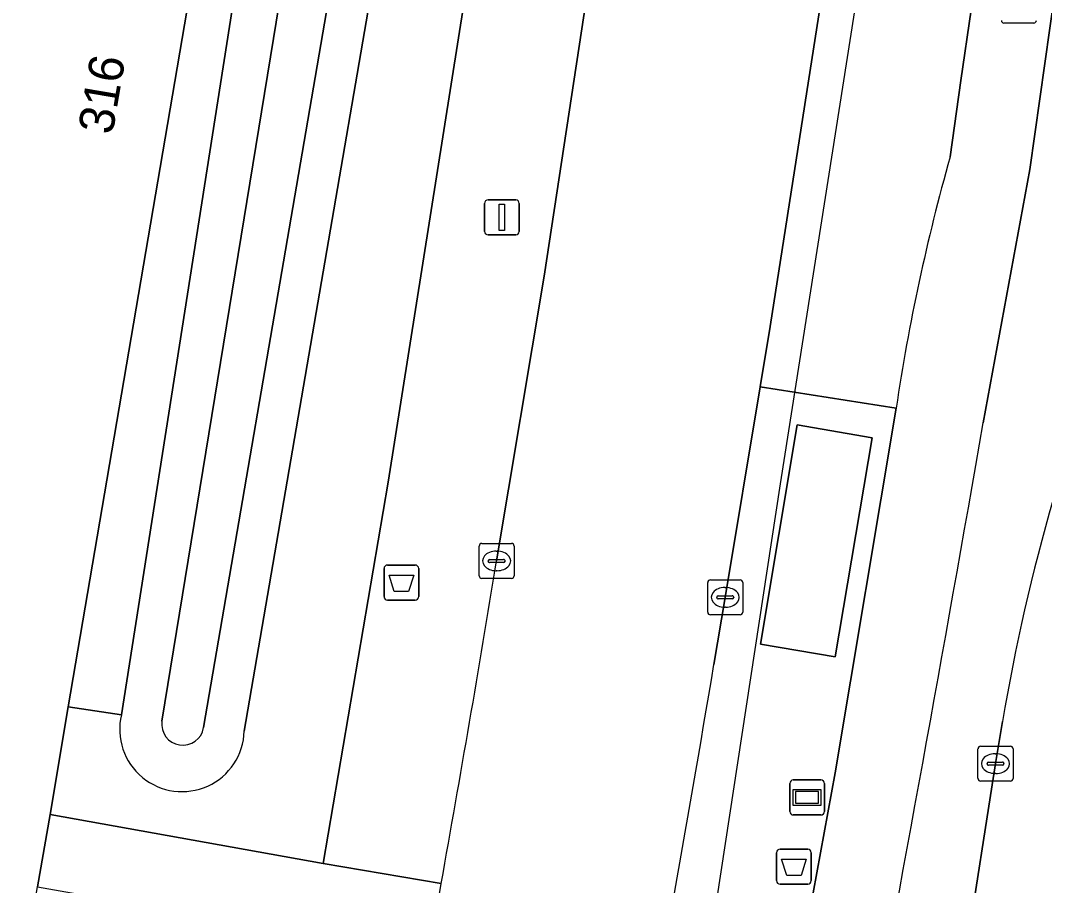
# Model space of a CAD drawing. Extents: x 161090 to 161692, y 379509 to 380907.
# Drawn here: x 161509.63 to 161538.89, y 379865.66 to 379890.39 of the extents above; entities that cross this region are included whole.
import ezdxf

# ---------------------------------------------------------------- set-up
doc = ezdxf.new("R2010")
doc.units = 0
for name, color, linetype in [('IMGEO_Afvalbak', 7, 'Continuous'), ('IMGEO_Berm_groen', 7, 'Continuous'), ('IMGEO_Fietspad_gesloten', 7, 'Continuous'), ('IMGEO_Groenvoorziening', 7, 'Continuous'), ('IMGEO_Hek', 7, 'Continuous'), ('IMGEO_Informatiebord', 7, 'Continuous'), ('IMGEO_Kolk', 7, 'Continuous'), ('IMGEO_Lichtmast', 7, 'Continuous'), ('IMGEO_Oever', 7, 'Continuous'), ('IMGEO_OVBaan_gesloten', 7, 'Continuous'), ('IMGEO_Pand', 7, 'Continuous'), ('IMGEO_Pand_nummerreeks', 7, 'Continuous'), ('IMGEO_Rijbaan_regionaal_gesloten', 7, 'Continuous'), ('IMGEO_Rioolput', 7, 'Continuous'), ('IMGEO_Voetpad_open', 7, 'Continuous'), ('IMGEO_Waterloop', 7, 'Continuous')]:
    doc.layers.add(name, color=color, linetype=linetype)

msp = doc.modelspace()

# ---------------------------------------------------------------- linework, layer by layer
at = {"layer": 'IMGEO_Afvalbak'}
for p, q in [((161520.021, 379873.924), (161520.021, 379874.724)), ((161520.021, 379874.724), (161520.021, 379873.924)), ((161520.121, 379874.824), (161520.911, 379874.824)), ((161520.911, 379874.824), (161520.121, 379874.824)), ((161521.011, 379874.724), (161521.011, 379873.924)), ((161521.011, 379873.924), (161521.011, 379874.724)), ((161520.911, 379873.824), (161520.121, 379873.824)), ((161520.121, 379873.824), (161520.911, 379873.824)), ((161531.238, 379865.802), (161531.238, 379866.602)), ((161531.238, 379866.602), (161531.238, 379865.802)), ((161531.338, 379866.702), (161532.128, 379866.702)), ((161532.128, 379866.702), (161531.338, 379866.702)), ((161532.228, 379866.602), (161532.228, 379865.802)), ((161532.228, 379865.802), (161532.228, 379866.602)), ((161532.128, 379865.702), (161531.338, 379865.702)), ((161531.338, 379865.702), (161532.128, 379865.702))]:
    msp.add_line(p, q, dxfattribs=at)
for points in [[(161520.164, 379874.538), (161520.868, 379874.538), (161520.719, 379874.068), (161520.313, 379874.068), (161520.164, 379874.538)], [(161531.381, 379866.416), (161532.085, 379866.416), (161531.936, 379865.946), (161531.53, 379865.946), (161531.381, 379866.416)]]:
    msp.add_lwpolyline(points, dxfattribs=at)
for centre, start, end in [((161520.121, 379874.724), 90, 180), ((161520.121, 379874.724), 90, 180), ((161520.911, 379874.724), 0, 90), ((161520.911, 379874.724), 360, 90), ((161520.121, 379873.924), 180, 270), ((161520.121, 379873.924), 180, 270), ((161520.911, 379873.924), 270, 0), ((161520.911, 379873.924), 270, 0), ((161531.338, 379866.602), 90, 180), ((161531.338, 379866.602), 90, 180), ((161532.128, 379866.602), 0, 90), ((161532.128, 379866.602), 360, 90), ((161531.338, 379865.802), 180, 270), ((161531.338, 379865.802), 180, 270), ((161532.128, 379865.802), 270, 0), ((161532.128, 379865.802), 270, 0)]:
    msp.add_arc(centre, 0.1, start, end, dxfattribs=at)
at = {"layer": 'IMGEO_Berm_groen'}
for points in [[(161558.722, 379967.648), (161555.358, 379965.446), (161553.331, 379964.003), (161549.893, 379961.557), (161549.238, 379957.378), (161540.382, 379899.28), (161539.192, 379891.189), (161538.475, 379886.135), (161537.144, 379878.891)], [(161536.505, 379888.676), (161536.797, 379890.693), (161532.543, 379891.174), (161531.052, 379881.64), (161530.767, 379879.919), (161534.655, 379879.312)], [(161536.195, 379886.489), (161536.505, 379888.676)], [(161529.831, 379840.039), (161527.896, 379830.664), (161527.892, 379830.638), (161530.874, 379830.07), (161530.88, 379830.1), (161531.532, 379833.673), (161534.094, 379847.687), (161534.951, 379852.858), (161537.493, 379869.147), (161537.692, 379870.348)]]:
    msp.add_lwpolyline(points, dxfattribs=at)
for centre, radius, start, end in [((161592.248, 379870.708), 58.233, 164.2759, 171.50297), ((161592.383, 379861.226), 55.446, 157.0586, 170.5303), ((160061.28, 380136.574), 1498.191, 348.584122, 350.096087)]:
    msp.add_arc(centre, radius, start, end, dxfattribs=at)
at = {"layer": 'IMGEO_Fietspad_gesloten'}
for points in [[(161597.182, 380280.466), (161595.455, 380269.727), (161595.124, 380267.672), (161594.731, 380265.142), (161581.225, 380178.309), (161575.364, 380140.757), (161574.544, 380135.394), (161573.298, 380127.137), (161570.943, 380112.605), (161564.94, 380073.828), (161547.32, 379960.011), (161538.081, 379899.575), (161536.797, 379890.693), (161536.505, 379888.676), (161536.195, 379886.489)], [(161537.144, 379878.891), (161538.475, 379886.135), (161539.192, 379891.189), (161540.382, 379899.28), (161549.238, 379957.378), (161549.893, 379961.557), (161550.626, 379966.233), (161554.52, 379991.079)], [(161534.655, 379879.312), (161532.909, 379868.886), (161531.551, 379861.452), (161529.758, 379851.957), (161525.498, 379831.145), (161524.736, 379828.031), (161522.815, 379820.18), (161522.849, 379819.177)]]:
    msp.add_lwpolyline(points, dxfattribs=at)
for centre, radius, start, end in [((161592.248, 379870.708), 58.233, 164.2759, 171.50297), ((160061.28, 380136.574), 1498.191, 348.584122, 350.096087)]:
    msp.add_arc(centre, radius, start, end, dxfattribs=at)
at = {"layer": 'IMGEO_Groenvoorziening'}
for points in [[(161523.024, 379912.682), (161521.974, 379904.714), (161516.028, 379870.076)], [(161517.782, 379910.612), (161511, 379870.768), (161512.517, 379870.541), (161515.837, 379891.688)], [(161512.517, 379870.541), (161511, 379870.768), (161510.477, 379867.696), (161518.281, 379866.292), (161520.143, 379877.191), (161522.931, 379894.837)]]:
    msp.add_lwpolyline(points, dxfattribs=at)
msp.add_arc((161514.248, 379870.127), 1.78, 166.5509, 358.3603, dxfattribs=at)
at = {"layer": 'IMGEO_Hek'}
msp.add_lwpolyline([(161570.009, 380123.365), (161550.635, 380000), (161531.34, 379877.143), (161526.851, 379847.795)], dxfattribs=at)
at = {"layer": 'IMGEO_Informatiebord'}
for p, q in [((161531.613, 379867.78), (161531.613, 379868.58)), ((161531.613, 379868.58), (161531.613, 379867.78)), ((161531.713, 379868.68), (161532.503, 379868.68)), ((161532.503, 379868.68), (161531.713, 379868.68)), ((161532.603, 379868.58), (161532.603, 379867.78)), ((161532.603, 379867.78), (161532.603, 379868.58)), ((161532.503, 379867.68), (161531.713, 379867.68)), ((161531.713, 379867.68), (161532.503, 379867.68))]:
    msp.add_line(p, q, dxfattribs=at)
for points in [[(161531.714, 379868.412), (161532.502, 379868.412), (161532.502, 379867.948), (161531.714, 379867.948), (161531.714, 379868.412)], [(161531.779, 379868.347), (161531.779, 379868.013), (161532.437, 379868.013), (161532.437, 379868.347), (161531.779, 379868.347)]]:
    msp.add_lwpolyline(points, dxfattribs=at)
for centre, start, end in [((161531.713, 379868.58), 90, 180), ((161531.713, 379868.58), 90, 180), ((161532.503, 379868.58), 0, 90), ((161532.503, 379868.58), 360, 90), ((161531.713, 379867.78), 180, 270), ((161531.713, 379867.78), 180, 270), ((161532.503, 379867.78), 270, 0), ((161532.503, 379867.78), 270, 0)]:
    msp.add_arc(centre, 0.1, start, end, dxfattribs=at)
at = {"layer": 'IMGEO_Kolk'}
for p, q in [((161522.738, 379874.516), (161522.738, 379875.368)), ((161522.813, 379875.442), (161523.665, 379875.442)), ((161523.739, 379875.368), (161523.739, 379874.516)), ((161523.226, 379875.222), (161523.251, 379875.222)), ((161522.997, 379874.936), (161522.997, 379874.948)), ((161523.435, 379874.899), (161523.037, 379874.899)), ((161523.04, 379874.985), (161523.438, 379874.985)), ((161523.481, 379874.948), (161523.481, 379874.936)), ((161523.665, 379874.442), (161522.813, 379874.442)), ((161523.249, 379874.662), (161523.224, 379874.662)), ((161529.27, 379873.475), (161529.27, 379874.327)), ((161529.345, 379874.401), (161530.197, 379874.401)), ((161529.758, 379874.181), (161529.783, 379874.181)), ((161530.271, 379874.327), (161530.271, 379873.475)), ((161529.529, 379873.895), (161529.529, 379873.907)), ((161529.967, 379873.858), (161529.569, 379873.858)), ((161529.572, 379873.944), (161529.97, 379873.944)), ((161530.013, 379873.907), (161530.013, 379873.895)), ((161529.781, 379873.621), (161529.756, 379873.621)), ((161530.197, 379873.401), (161529.345, 379873.401)), ((161536.992, 379868.721), (161536.992, 379869.573)), ((161537.067, 379869.647), (161537.919, 379869.647)), ((161537.993, 379869.573), (161537.993, 379868.721)), ((161537.251, 379869.141), (161537.251, 379869.153)), ((161537.294, 379869.19), (161537.692, 379869.19)), ((161537.48, 379869.427), (161537.505, 379869.427)), ((161537.735, 379869.153), (161537.735, 379869.141)), ((161537.689, 379869.104), (161537.291, 379869.104)), ((161537.503, 379868.867), (161537.478, 379868.867)), ((161537.919, 379868.647), (161537.067, 379868.647))]:
    msp.add_line(p, q, dxfattribs=at)
for points in [[(161522.738, 379874.516), (161522.738, 379875.368)], [(161522.813, 379875.442), (161523.665, 379875.442)], [(161523.739, 379875.368), (161523.739, 379874.516)], [(161523.665, 379874.442), (161522.813, 379874.442)], [(161529.27, 379873.475), (161529.27, 379874.327)], [(161529.345, 379874.401), (161530.197, 379874.401)], [(161530.271, 379874.327), (161530.271, 379873.475)], [(161530.197, 379873.401), (161529.345, 379873.401)], [(161536.992, 379868.721), (161536.992, 379869.573)], [(161537.067, 379869.647), (161537.919, 379869.647)], [(161537.993, 379869.573), (161537.993, 379868.721)], [(161537.919, 379868.647), (161537.067, 379868.647)]]:
    msp.add_lwpolyline(points, dxfattribs=at)
for centre, radius, start, end in [((161522.815, 379875.366), 0.0765, 91.552, 178.448), ((161522.815, 379875.366), 0.0765, 91.552, 178.448), ((161523.663, 379875.366), 0.0765, 1.552, 88.448), ((161523.663, 379875.366), 0.0765, 1.552, 88.448), ((161523.037, 379874.945), 0.0403, 85.8775, 175.7526), ((161523.034, 379874.935), 0.0366, 178.938, 274.7102), ((161523.438, 379874.942), 0.043, 264.8664, 352.4533), ((161523.442, 379874.947), 0.0386, 1.7309, 96.639), ((161522.815, 379874.518), 0.0765, 181.552, 268.448), ((161522.815, 379874.518), 0.0765, 181.552, 268.448), ((161523.663, 379874.518), 0.0765, 271.552, 358.448), ((161523.663, 379874.518), 0.0765, 271.552, 358.448), ((161529.347, 379874.325), 0.0765, 91.552, 178.448), ((161529.347, 379874.325), 0.0765, 91.552, 178.448), ((161530.195, 379874.325), 0.0765, 1.552, 88.448), ((161530.195, 379874.325), 0.0765, 1.552, 88.448), ((161529.569, 379873.904), 0.0403, 85.8775, 175.7526), ((161529.566, 379873.894), 0.0366, 178.938, 274.7102), ((161529.97, 379873.901), 0.043, 264.8664, 352.4533), ((161529.974, 379873.906), 0.0386, 1.7309, 96.639), ((161529.347, 379873.477), 0.0765, 181.552, 268.448), ((161529.347, 379873.477), 0.0765, 181.552, 268.448), ((161530.195, 379873.477), 0.0765, 271.552, 358.448), ((161530.195, 379873.477), 0.0765, 271.552, 358.448), ((161537.069, 379869.571), 0.0765, 91.552, 178.448), ((161537.069, 379869.571), 0.0765, 91.552, 178.448), ((161537.917, 379869.571), 0.0765, 1.552, 88.448), ((161537.917, 379869.571), 0.0765, 1.552, 88.448), ((161537.291, 379869.15), 0.0403, 85.8775, 175.7526), ((161537.696, 379869.152), 0.0386, 1.7309, 96.639), ((161537.288, 379869.14), 0.0366, 178.938, 274.7102), ((161537.692, 379869.147), 0.043, 264.8664, 352.4533), ((161537.069, 379868.723), 0.0765, 181.552, 268.448), ((161537.069, 379868.723), 0.0765, 181.552, 268.448), ((161537.917, 379868.723), 0.0765, 271.552, 358.448), ((161537.917, 379868.723), 0.0765, 271.552, 358.448)]:
    msp.add_arc(centre, radius, start, end, dxfattribs=at)
for centre, major_axis, ratio, start_param, end_param in [((161523.225, 379874.942), (-0.387, 0.002), 0.722429, 4.712389, 7.853982), ((161523.25, 379874.942), (-0.39, 0.002), 0.717154, 1.570796, 4.712389), ((161529.757, 379873.901), (-0.387, 0.002), 0.722429, 4.712389, 7.853982), ((161529.782, 379873.901), (-0.39, 0.002), 0.717154, 1.570796, 4.712389), ((161537.479, 379869.147), (-0.387, 0.002), 0.722429, 4.712389, 7.853982), ((161537.504, 379869.147), (-0.39, 0.002), 0.717154, 1.570796, 4.712389)]:
    msp.add_ellipse(centre, major_axis=major_axis, ratio=ratio, start_param=start_param, end_param=end_param, dxfattribs=at)
at = {"layer": 'IMGEO_Lichtmast'}
for p, q in [((161522.993, 379885.263), (161523.783, 379885.263)), ((161523.783, 379885.263), (161522.993, 379885.263)), ((161522.893, 379884.363), (161522.893, 379885.163)), ((161522.893, 379885.163), (161522.893, 379884.363)), ((161523.883, 379885.163), (161523.883, 379884.363)), ((161523.883, 379884.363), (161523.883, 379885.163)), ((161523.783, 379884.263), (161522.993, 379884.263)), ((161522.993, 379884.263), (161523.783, 379884.263))]:
    msp.add_line(p, q, dxfattribs=at)
msp.add_lwpolyline([(161523.313, 379885.138), (161523.463, 379885.138), (161523.463, 379884.388), (161523.313, 379884.388), (161523.313, 379885.138)], dxfattribs=at)
for centre, start, end in [((161522.993, 379885.163), 90, 180), ((161522.993, 379885.163), 90, 180), ((161523.783, 379885.163), 0, 90), ((161523.783, 379885.163), 360, 90), ((161522.993, 379884.363), 180, 270), ((161522.993, 379884.363), 180, 270), ((161523.783, 379884.363), 270, 0), ((161523.783, 379884.363), 270, 0)]:
    msp.add_arc(centre, 0.1, start, end, dxfattribs=at)
at = {"layer": 'IMGEO_Oever'}
for points in [[(161519.482, 379913.207), (161515.837, 379891.688), (161512.517, 379870.541)], [(161513.673, 379870.36), (161520.632, 379912.951)], [(161521.864, 379912.835), (161520.821, 379904.912), (161514.867, 379870.178)], [(161516.028, 379870.076), (161521.974, 379904.714), (161523.024, 379912.682)]]:
    msp.add_lwpolyline(points, dxfattribs=at)
for centre, radius, start, end in [((161514.248, 379870.127), 1.78, 166.5509, 358.3603), ((161514.271, 379870.278), 0.604, 172.2126, 350.4538)]:
    msp.add_arc(centre, radius, start, end, dxfattribs=at)
at = {"layer": 'IMGEO_OVBaan_gesloten'}
for points in [[(161529.449, 379871.979), (161529.771, 379873.901), (161530.767, 379879.919), (161531.052, 379881.64), (161532.543, 379891.174), (161533.152, 379895.072), (161536.563, 379917.273), (161539.958, 379939.476), (161541.406, 379948.743), (161543.025, 379959.699), (161544.637, 379970.686), (161546.186, 379981.488)], [(161537.983, 379971.128), (161536.498, 379960.739), (161535.873, 379956.523), (161534.566, 379947.954), (161534.462, 379947.272), (161533.448, 379940.484), (161531.848, 379929.997), (161531.665, 379928.747), (161531.614, 379928.422), (161528.781, 379910.215), (161528.578, 379908.95), (161527.971, 379905.065), (161526.727, 379897.107), (161524.592, 379883.079), (161523.239, 379874.942)]]:
    msp.add_lwpolyline(points, dxfattribs=at)
for centre, radius, start, end in [((160912.449, 379975.076), 618.943, 349.823773, 350.689677), ((160815.518, 379992.315), 724.001, 348.19286, 350.43251), ((160897.259, 379977.712), 634.361, 349.399884, 349.831828)]:
    msp.add_arc(centre, radius, start, end, dxfattribs=at)
at = {"layer": 'IMGEO_Pand'}
msp.add_lwpolyline([(161509.633, 379862.736), (161510.124, 379865.623), (161510.477, 379867.696), (161511, 379870.768), (161517.782, 379910.612)], dxfattribs=at)
at = {"layer": 'IMGEO_Rijbaan_regionaal_gesloten'}
msp.add_lwpolyline([(161537.692, 379870.348), (161537.493, 379869.147), (161534.951, 379852.858), (161534.094, 379847.687), (161531.532, 379833.673), (161530.88, 379830.1), (161530.874, 379830.07), (161530.32, 379827.002)], dxfattribs=at)
msp.add_arc((161592.383, 379861.226), 55.446, 157.0586, 170.5303, dxfattribs=at)
at = {"layer": 'IMGEO_Rioolput'}
msp.add_line((161538.587, 379890.318), (161537.735, 379890.318), dxfattribs=at)
msp.add_lwpolyline([(161538.587, 379890.318), (161537.735, 379890.318)], dxfattribs=at)
for centre, start, end in [((161537.737, 379890.394), 181.552, 268.448), ((161537.737, 379890.394), 181.552, 268.448), ((161538.585, 379890.394), 271.552, 358.448), ((161538.585, 379890.394), 271.552, 358.448)]:
    msp.add_arc(centre, 0.0765, start, end, dxfattribs=at)
at = {"layer": 'IMGEO_Voetpad_open'}
for points in [[(161526.727, 379897.107), (161527.971, 379905.065), (161524.586, 379905.575), (161522.931, 379894.837), (161520.143, 379877.191), (161518.281, 379866.292), (161521.656, 379865.723)], [(161523.239, 379874.942), (161524.592, 379883.079), (161526.727, 379897.107)], [(161534.655, 379879.312), (161530.767, 379879.919), (161529.771, 379873.901), (161529.449, 379871.979)], [(161521.694, 379832.034), (161525.498, 379831.145), (161529.758, 379851.957), (161531.551, 379861.452), (161532.909, 379868.886), (161534.655, 379879.312)], [(161521.656, 379865.723), (161518.281, 379866.292), (161510.477, 379867.696), (161510.124, 379865.623), (161517.962, 379864.248), (161517.184, 379860.149)]]:
    msp.add_lwpolyline(points, dxfattribs=at)
for points in [[(161530.774, 379872.561), (161531.828, 379878.831), (161533.973, 379878.461), (161532.914, 379872.197)], [(161530.774, 379872.561), (161532.914, 379872.197), (161533.973, 379878.461), (161531.828, 379878.831)]]:
    msp.add_lwpolyline(points, close=True, dxfattribs=at)
for centre, radius, start, end in [((160912.449, 379975.076), 618.943, 349.823773, 350.689677), ((160815.518, 379992.315), 724.001, 348.19286, 350.43251), ((160897.259, 379977.712), 634.361, 349.399884, 349.831828)]:
    msp.add_arc(centre, radius, start, end, dxfattribs=at)
at = {"layer": 'IMGEO_Waterloop'}
for points in [[(161520.632, 379912.951), (161513.673, 379870.36)], [(161514.867, 379870.178), (161520.821, 379904.912), (161521.864, 379912.835)]]:
    msp.add_lwpolyline(points, dxfattribs=at)
msp.add_arc((161514.271, 379870.278), 0.604, 172.2126, 350.4538, dxfattribs=at)

# ---------------------------------------------------------------- texts
at = {"layer": 'IMGEO_Pand_nummerreeks'}
msp.add_text('316', height=1, rotation=80.3401, dxfattribs=at).set_placement((161512.258, 379887.102))

doc.saveas('drawing.dxf')
